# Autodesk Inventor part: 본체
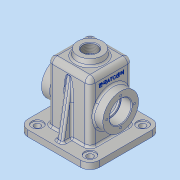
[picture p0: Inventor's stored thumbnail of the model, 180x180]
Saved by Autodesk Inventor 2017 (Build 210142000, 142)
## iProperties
Part Number: 본체
Material: 알루미늄 6061
Document SubType Name: Modeling
Designer: MRC
Density: 2.7 g/cm^3
Appearance: 알루미늄 - 평지
Mass: 753.623 g
Surface Area: 864.209 cm^2
Volume: 279.12 cm^3
Author: MRC
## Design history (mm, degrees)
sketch "스케치1"
  geometry: L1 (-34, 53)-(34, 53); L2 (34, 53)-(34, -52); L3 (34, -52)-(-34, -52); L4 (-34, -52)-(-34, 53); 2 further points
  constraints: 8 end point, 2 parallel, 1 horizontal, 1 midpoint, 1 perpendicular, 1 vertical alignment
  dimensions: "d0" = 52 distance from line of L3 point (0, 0); "d1" = 105 distance of L3.end L1.start; "d2" = 68 distance of L1.start L1.end
extrude "돌출1" new body sketch "스케치1" stored distance "d3" = 68; taper "d4" = 0 deg
fillet "모깎기1" dims "d5" = 8
fillet "모깎기2" dims "d6" = 8
feature "쉘1" dims "d7" = 5
sketch "스케치3"
  geometry: C1 r 28.5 at (26, 52); 1 further point
  constraints: 1 centre point, 1 coincident
  dimensions: "d8" = 57 diameter of C1
extrude "돌출2" join sketch "스케치3" distance "d9" = 15; taper "d11" = 0 deg; dims "d10" = 3, "d12" = 0
hole "구멍1" diameter "d15" = 30; stored, may be unused: countersink angle "d19" = 90 deg, drill point angle "d21" = 118 deg; dims "d13" = 10, "d14" = 10, "d16" = 6, "d17" = 35, "d18" = 17, "d20" = 30
sketch "스케치4"
  geometry: C1 r 17.5 at (0, 0) reference; 1 further point
  constraints: 1 vertical alignment
  dimensions: "d22" = 22 distance of C1.centre point (0, 22)
hole "구멍2" sketch "스케치4" at (0, 22) diameter "d23" = 3.242; stored, may be unused: countersink angle "d27" = 90 deg, drill point angle "d29" = 118 deg; dims "d24" = 8, "d25" = 35, "d26" = 17, "d28" = 10
sketch "스케치6"
  geometry: L1 (-8, 60)-(-8, 8) reference; L2 (52, 0)-(0, 0) reference; L3 (60, 60)-(60, 8) reference; L4 (0, 68)-(52, 68) reference; L5 (83, -23)-(-31, -23); L6 (-31, -23)-(-31, 91); L7 (-31, 91)-(83, 91); L8 (83, 91)-(83, -23); L9 (83, -23)-(-31, 91); L10 (-31, -23)-(83, 91); A1 r 8 centre (0, 60) between (0, 68) and (-8, 60) reference; A2 r 8 centre (0, 8) between (-8, 8) and (0, 0) reference; A3 r 8 centre (52, 8) between (52, 0) and (60, 8) reference; A4 r 8 centre (52, 60) between (60, 60) and (52, 68) reference; 1 further point
  constraints: 12 end point, 2 midpoint, 2 parallel, 1 horizontal, 1 perpendicular
  dimensions: "d45" = 114 distance of L6.end L7.end; "d46" = 114 distance of L5.end L6.end
extrude "돌출4" join sketch "스케치6" distance "d47" = 10; taper "d48" = 0 deg
fillet "모깎기3" dims "d49" = 15
sketch "스케치7"
  geometry: A1 r 15 centre (-16, 8) between (-16, 23) and (-31, 8) reference; A2 r 15 centre (-16, -76) between (-31, -76) and (-16, -91) reference; A3 r 15 centre (68, -76) between (68, -91) and (83, -76) reference; A4 r 15 centre (68, 8) between (83, 8) and (68, 23) reference; 5 further points
  constraints: 4 coincident
hole "구멍4" sketch "스케치7" at (-16, 8), (68, 8), (68, -76), (-16, -76) diameter "d50" = 10; stored, may be unused: countersink angle "d54" = 90 deg, drill point angle "d56" = 118 deg; dims "d51" = 50, "d52" = 18, "d53" = 2, "d55" = 59.3
sketch "스케치8"
  geometry: L1 (45, -34)-(-42, -34) reference; L2 (-42, -33)-(-42, -51) reference; L3 (-42, -42)-(-42, -57) reference; L4 (43.069, -34)-(-42, -49); L5 (-42, -57)-(-52, -57) reference; 1 further point
  constraints: 2 end point, 2 point on line
  dimensions: "d57" = 8 distance of L4.end L3.end; "d58" = 10 deg angle of L5 L4
feature "리브1" sketch "스케치8" dims "d59" = 1, "d60" = 10, "d61" = 0, "d62" = 0, "d63" = 1, "d64" = 1
sketch "스케치9"
  geometry: L1 (-8, 0)-(-8, -87) reference; L2 (46, 18)-(6, 18) reference; 1 further point
  constraints: 1 other
  dimensions: "d65" = 34 distance from line of L1 point (26, -7); "d66" = 25 distance from line of L2 point (26, -7)
feature "엠보싱1" sketch "스케치9" dims "d0" = 52, "d1" = 105, "d2" = 68, "d67" = 0.5, "d68" = 0
fillet "모깎기4" dims "d69" = 3
fillet "모깎기5" dims "d70" = 3
fillet "모깎기6" dims "d71" = 3
chamfer "모따기1" distance "d72" = 1; stored, may be unused: second distance "d73" = 2, angle "d74" = 45 deg
fillet "모깎기7" dims "d75" = 0.3
node "작업 평면1"
sketch "스케치10"
  geometry: C1 r 20 at (-42, 57); 1 further point
  constraints: 1 centre point, 1 coincident
  dimensions: "d77" = 40 diameter of C1
extrude "돌출5" join sketch "스케치10" stored distance "d78" = 40 (= d77); taper "d79" = 8 deg
hole "구멍5" diameter "d82" = 22.835; stored, may be unused: countersink angle "d86" = 90 deg, drill point angle "d88" = 118 deg; dims "d80" = 10, "d81" = 10, "d83" = 50, "d84" = 18, "d85" = 2, "d87" = 59.3
fillet "모깎기8" dims "d89" = 3
chamfer "모따기2" distance "d90" = 1; stored, may be unused: second distance "d91" = 2, angle "d92" = 45 deg
node "솔리드1"
pattern_circular "원형 패턴1" dims angle "d31" = 360 deg
mirror "미러1"
mirror "미러2"
other parameters: "d76" = -115
